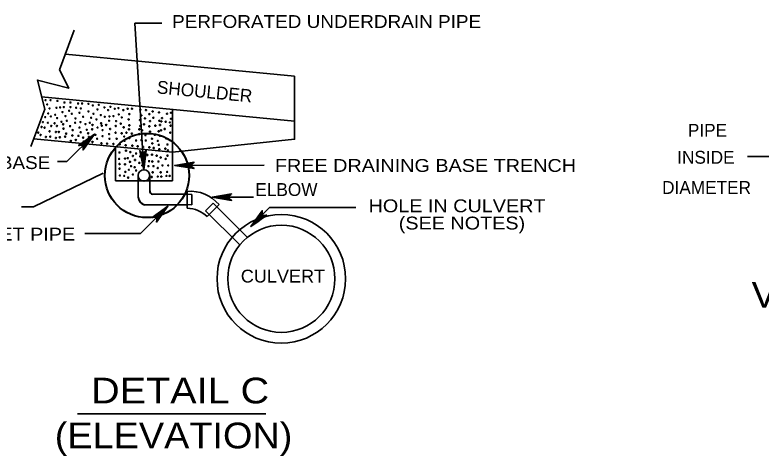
# Model space of a CAD drawing. Extents: x -48732 to -48696.6, y -117659.8 to -117637.8.
# Drawn here: x -48717.26 to -48710.3, y -117653.09 to -117648.97 of the extents above; entities that cross this region are included whole.
import ezdxf

# ---------------------------------------------------------------- set-up
doc = ezdxf.new("R2010")
doc.units = 0
doc.header["$LTSCALE"] = 0.048
doc.layers.add('1', color=7, linetype='Continuous', lineweight=25)
doc.layers.add('3', color=7, linetype='Continuous', lineweight=35)

msp = doc.modelspace()

# ---------------------------------------------------------------- linework, layer by layer
at = {"layer": '1', "lineweight": 40}
msp.add_circle((-48716.02774, -117650.47144), 0.39328, dxfattribs=at)
for centre, radius, end in [((-48716.03983, -117650.67442), 0.07, 262.57442), ((-48715.97183, -117650.61475), 0.03, 262.57441)]:
    msp.add_arc(centre, radius, 180, end, dxfattribs=at)
at = {"layer": '3'}
for p, q in [((-48716.05583, -117650.41717), (-48716.14042, -117649.0505)), ((-48716.14042, -117649.0505), (-48715.89042, -117649.0505)), ((-48716.70642, -117649.1155), (-48716.84342, -117649.4845)), ((-48716.78942, -117649.3385), (-48714.65075, -117649.5445)), ((-48717.01042, -117649.7365), (-48714.65075, -117649.96417)), ((-48716.98042, -117649.8515), (-48717.11042, -117650.1995)), ((-48716.77433, -117650.34067), (-48716.51842, -117650.08475)), ((-48716.32042, -117650.20225), (-48716.32042, -117650.5225)), ((-48715.78942, -117650.2535), (-48715.78942, -117650.5225)), ((-48710.10058, -117650.29358), (-48710.42558, -117650.29358)), ((-48716.86242, -117650.34067), (-48716.77433, -117650.34067)), ((-48715.76825, -117650.37733), (-48715.62425, -117650.37733)), ((-48715.73125, -117650.37733), (-48714.93433, -117650.374)), ((-48717.088, -117650.7625), (-48716.43608, -117650.44833)), ((-48716.32042, -117650.5225), (-48715.78942, -117650.5225)), ((-48716.10983, -117650.47117), (-48716.10983, -117650.67442)), ((-48716.00183, -117650.47117), (-48716.00183, -117650.61475)), ((-48715.97575, -117650.6445), (-48715.65158, -117650.6445)), ((-48715.65142, -117650.61958), (-48715.65242, -117650.77558)), ((-48715.65158, -117650.6445), (-48715.60942, -117650.64858)), ((-48715.60942, -117650.64858), (-48715.61042, -117650.74658)), ((-48716.04892, -117650.74383), (-48715.65158, -117650.74383)), ((-48715.65217, -117650.7425), (-48715.61042, -117650.74658)), ((-48715.41042, -117650.73058), (-48715.48042, -117650.80058)), ((-48715.35542, -117650.74358), (-48715.46642, -117650.85458)), ((-48715.09342, -117651.04658), (-48715.41042, -117650.73058)), ((-48717.19942, -117650.7625), (-48717.088, -117650.7625)), ((-48716.08808, -117651.01383), (-48715.83217, -117650.75792)), ((-48715.16342, -117651.11658), (-48715.48042, -117650.80058)), ((-48715.05842, -117650.94858), (-48714.88342, -117650.77158)), ((-48714.88342, -117650.77158), (-48714.07942, -117650.77158)), ((-48716.60667, -117651.01383), (-48716.08808, -117651.01383)), ((-48716.67542, -117652.69492), (-48714.92042, -117652.69492))]:
    msp.add_line(p, q, dxfattribs=at)
for points in [[(-48716.84342, -117649.4845), (-48716.75742, -117649.6575), (-48717.05042, -117649.5815), (-48716.98042, -117649.8515)], [(-48715.78942, -117650.2535), (-48714.65075, -117650.13283), (-48714.65075, -117649.5445)], [(-48717.08442, -117650.1285), (-48715.78942, -117650.2535), (-48715.78942, -117649.8545)], [(-48716.62442, -117650.23275), (-48716.51842, -117650.08475), (-48716.66642, -117650.19075), (-48716.66142, -117650.19075), (-48716.53142, -117650.09775), (-48716.62442, -117650.22775), (-48716.62342, -117650.22175), (-48716.54442, -117650.11075), (-48716.65542, -117650.18975), (-48716.64942, -117650.18875), (-48716.55742, -117650.12375), (-48716.62242, -117650.21575), (-48716.62242, -117650.20975), (-48716.57042, -117650.13675), (-48716.64342, -117650.18875), (-48716.63742, -117650.18775), (-48716.58242, -117650.14875), (-48716.62142, -117650.20375), (-48716.62142, -117650.19775), (-48716.59542, -117650.16175), (-48716.63142, -117650.18775), (-48716.62542, -117650.18675), (-48716.60842, -117650.17475), (-48716.62042, -117650.19175), (-48716.62442, -117650.23275), (-48716.62042, -117650.18675), (-48716.66642, -117650.19075)], [(-48716.09517, -117650.239), (-48716.05583, -117650.41717), (-48716.03525, -117650.23592), (-48716.03892, -117650.24117), (-48716.05667, -117650.39925), (-48716.091, -117650.24283), (-48716.08667, -117650.24767), (-48716.05767, -117650.38025), (-48716.04283, -117650.24533), (-48716.04558, -117650.25042), (-48716.05867, -117650.36225), (-48716.08342, -117650.25242), (-48716.07933, -117650.25617), (-48716.05967, -117650.34433), (-48716.04933, -117650.25467), (-48716.05308, -117650.25992), (-48716.06058, -117650.32633), (-48716.075, -117650.261), (-48716.07083, -117650.26475), (-48716.06158, -117650.30733), (-48716.05683, -117650.26408), (-48716.06058, -117650.26925), (-48716.0625, -117650.28942), (-48716.06658, -117650.26958), (-48716.09517, -117650.239), (-48716.06333, -117650.27342), (-48716.03525, -117650.23592)], [(-48715.58825, -117650.34733), (-48715.76825, -117650.37733), (-48715.58825, -117650.40733), (-48715.59325, -117650.40333), (-48715.75025, -117650.37733), (-48715.59225, -117650.35133), (-48715.59725, -117650.35533), (-48715.73125, -117650.37733), (-48715.59725, -117650.39933), (-48715.60225, -117650.39633), (-48715.71325, -117650.37733), (-48715.60225, -117650.35833), (-48715.60625, -117650.36233), (-48715.69525, -117650.37733), (-48715.60625, -117650.39233), (-48715.61125, -117650.38833), (-48715.67725, -117650.37733), (-48715.61125, -117650.36633), (-48715.61525, -117650.37033), (-48715.65825, -117650.37733), (-48715.61525, -117650.38433), (-48715.62025, -117650.38033), (-48715.64025, -117650.37733), (-48715.62025, -117650.37433), (-48715.58825, -117650.34733), (-48715.62425, -117650.37733), (-48715.58825, -117650.40733)], [(-48715.23842, -117650.64358), (-48715.41842, -117650.67358), (-48715.23842, -117650.70358), (-48715.24342, -117650.69958), (-48715.40042, -117650.67358), (-48715.24242, -117650.64758), (-48715.24742, -117650.65158), (-48715.38142, -117650.67358), (-48715.24742, -117650.69558), (-48715.25242, -117650.69258), (-48715.36342, -117650.67358), (-48715.25242, -117650.65458), (-48715.25642, -117650.65858), (-48715.34542, -117650.67358), (-48715.25642, -117650.68858), (-48715.26142, -117650.68458), (-48715.32742, -117650.67358), (-48715.26142, -117650.66258), (-48715.26542, -117650.66658), (-48715.30842, -117650.67358), (-48715.26542, -117650.68058), (-48715.27042, -117650.67658), (-48715.29042, -117650.67358), (-48715.27042, -117650.67058), (-48715.23842, -117650.64358), (-48715.27442, -117650.67358), (-48715.23842, -117650.70358)], [(-48715.41842, -117650.67358), (-48715.27442, -117650.67358), (-48715.03342, -117650.67258)], [(-48715.93817, -117650.90592), (-48715.83217, -117650.75792), (-48715.98017, -117650.86392), (-48715.97517, -117650.86392), (-48715.84517, -117650.77092), (-48715.93817, -117650.90092), (-48715.93717, -117650.89492), (-48715.85817, -117650.78392), (-48715.96917, -117650.86292), (-48715.96317, -117650.86192), (-48715.87117, -117650.79692), (-48715.93617, -117650.88892), (-48715.93617, -117650.88292), (-48715.88417, -117650.80992), (-48715.95717, -117650.86192), (-48715.95117, -117650.86092), (-48715.89617, -117650.82192), (-48715.93517, -117650.87692), (-48715.93517, -117650.87092), (-48715.90917, -117650.83492), (-48715.94517, -117650.86092), (-48715.93917, -117650.85992), (-48715.92217, -117650.84792), (-48715.93417, -117650.86492), (-48715.93817, -117650.90592), (-48715.93417, -117650.85992), (-48715.98017, -117650.86392)], [(-48714.95242, -117650.80058), (-48715.05842, -117650.94858), (-48714.91042, -117650.84258), (-48714.91542, -117650.84258), (-48715.04542, -117650.93558), (-48714.95242, -117650.80558), (-48714.95342, -117650.81158), (-48715.03242, -117650.92258), (-48714.92142, -117650.84358), (-48714.92742, -117650.84458), (-48715.01942, -117650.90958), (-48714.95442, -117650.81758), (-48714.95442, -117650.82358), (-48715.00642, -117650.89658), (-48714.93342, -117650.84458), (-48714.93942, -117650.84558), (-48714.99442, -117650.88458), (-48714.95542, -117650.82958), (-48714.95542, -117650.83558), (-48714.98142, -117650.87158), (-48714.94542, -117650.84558), (-48714.95142, -117650.84658), (-48714.96842, -117650.85858), (-48714.95642, -117650.84158), (-48714.95242, -117650.80058), (-48714.95642, -117650.84658), (-48714.91042, -117650.84258)]]:
    msp.add_lwpolyline(points, dxfattribs=at)
msp.add_lwpolyline([(-48714.98142, -117650.89358), (-48715.05842, -117650.94858), (-48715.00442, -117650.87158)], close=True, dxfattribs=at)
for centre, radius in [((-48716.97383, -117649.76792), 0.00515), ((-48716.92733, -117649.76792), 0.00515), ((-48716.86217, -117649.77417), 0.00515), ((-48716.95833, -117649.80825), 0.00515), ((-48716.93658, -117649.8455), 0.00515), ((-48716.8715, -117649.83933), 0.00515), ((-48716.83733, -117649.83625), 0.00515), ((-48716.80325, -117649.83308), 0.00515), ((-48716.797, -117649.78967), 0.00515), ((-48716.74117, -117649.78967), 0.00515), ((-48716.74117, -117649.83308), 0.00515), ((-48716.68842, -117649.83933), 0.00515), ((-48716.66983, -117649.799), 0.00515), ((-48716.645, -117649.8455), 0.00515), ((-48716.63258, -117649.799), 0.00515), ((-48716.57367, -117649.80208), 0.00515), ((-48716.53333, -117649.81758), 0.00515), ((-48716.4775, -117649.81142), 0.00515), ((-48716.42475, -117649.83625), 0.00515), ((-48716.36892, -117649.83), 0.00515), ((-48716.29442, -117649.84242), 0.00515), ((-48716.949, -117649.89208), 0.00515), ((-48716.88383, -117649.9045), 0.00515), ((-48716.81558, -117649.87967), 0.00515), ((-48716.75358, -117649.86725), 0.00515), ((-48716.72875, -117649.89517), 0.00515), ((-48716.65742, -117649.88583), 0.00515), ((-48716.57367, -117649.87342), 0.00515), ((-48716.52708, -117649.89517), 0.00515), ((-48716.48992, -117649.85483), 0.00515), ((-48716.45883, -117649.90758), 0.00515), ((-48716.39058, -117649.861), 0.00515), ((-48716.32858, -117649.84867), 0.00515), ((-48716.29133, -117649.90142), 0.00515), ((-48716.24792, -117649.861), 0.00515), ((-48716.20758, -117649.84867), 0.00515), ((-48716.19208, -117649.89825), 0.00515), ((-48716.16725, -117649.84867), 0.00515), ((-48716.08967, -117649.85792), 0.00515), ((-48716.08042, -117649.91067), 0.00515), ((-48716.03692, -117649.861), 0.00515), ((-48716.00592, -117649.89825), 0.00515), ((-48715.97492, -117649.87342), 0.00515), ((-48715.916, -117649.88275), 0.00515), ((-48715.8415, -117649.89517), 0.00515), ((-48715.80425, -117649.88583), 0.00515), ((-48716.99867, -117649.97275), 0.00515), ((-48716.97692, -117649.92625), 0.00515), ((-48716.95208, -117649.979), 0.00515), ((-48716.92417, -117649.92), 0.00515), ((-48716.89008, -117649.98517), 0.00515), ((-48716.86525, -117649.9355), 0.00515), ((-48716.82492, -117649.96967), 0.00515), ((-48716.78767, -117649.91692), 0.00515), ((-48716.77533, -117649.96033), 0.00515), ((-48716.69775, -117649.979), 0.00515), ((-48716.69467, -117649.93867), 0.00515), ((-48716.64808, -117649.97275), 0.00515), ((-48716.62325, -117649.92308), 0.00515), ((-48716.56125, -117649.979), 0.00515), ((-48716.54883, -117649.93242), 0.00515), ((-48716.49917, -117649.94792), 0.00515), ((-48716.45575, -117649.98517), 0.00515), ((-48716.42167, -117649.92308), 0.00515), ((-48716.38133, -117649.96033), 0.00515), ((-48716.37817, -117649.92), 0.00515), ((-48716.341, -117649.91692), 0.00515), ((-48716.31617, -117649.9635), 0.00515), ((-48716.26342, -117649.92933), 0.00515), ((-48716.19825, -117649.94792), 0.00515), ((-48716.09283, -117649.95417), 0.00515), ((-48716.04625, -117649.93867), 0.00515), ((-48715.99975, -117649.9635), 0.00515), ((-48715.96875, -117649.93242), 0.00515), ((-48715.91283, -117649.96033), 0.00515), ((-48715.89425, -117649.96658), 0.00515), ((-48715.88808, -117649.9355), 0.00515), ((-48715.85392, -117649.96967), 0.00515), ((-48715.81358, -117649.97592), 0.00515), ((-48715.80425, -117649.94175), 0.00515), ((-48717.01108, -117650.01933), 0.00515), ((-48716.98317, -117650.0255), 0.00515), ((-48716.92108, -117650.01), 0.00515), ((-48716.86833, -117650.01), 0.00515), ((-48716.80942, -117649.9945), 0.00515), ((-48716.80633, -117650.03483), 0.00515), ((-48716.74446, -117650.01069), 0.00515), ((-48716.72096, -117650.04778), 0.00515), ((-48716.65704, -117650.02419), 0.00515), ((-48716.60158, -117649.99142), 0.00515), ((-48716.58979, -117650.04436), 0.00515), ((-48716.53929, -117650.04103), 0.00515), ((-48716.53642, -117650.00067), 0.00515), ((-48716.48888, -117650.02419), 0.00515), ((-48716.44958, -117650.00692), 0.00515), ((-48716.44179, -117650.04778), 0.00515), ((-48716.40813, -117650.00061), 0.00515), ((-48716.372, -117650.03792), 0.00515), ((-48716.31925, -117650.01), 0.00515), ((-48716.27275, -117649.98825), 0.00515), ((-48716.24483, -117650.02242), 0.00515), ((-48716.19517, -117650.04108), 0.00515), ((-48716.19208, -117650.00383), 0.00515), ((-48716.099, -117650.04108), 0.00515), ((-48716.08967, -117650.01), 0.00515), ((-48716.07417, -117650.05033), 0.00515), ((-48716.05558, -117649.9945), 0.00515), ((-48716.00592, -117650.01308), 0.00515), ((-48715.95008, -117650.00692), 0.00515), ((-48715.90667, -117650.00067), 0.00515), ((-48715.89733, -117650.05033), 0.00515), ((-48715.86325, -117650.03792), 0.00515), ((-48715.80742, -117650.00692), 0.00515), ((-48717.04208, -117650.07208), 0.00515), ((-48717.02033, -117650.09383), 0.00515), ((-48716.97075, -117650.11242), 0.00515), ((-48716.93658, -117650.05967), 0.00515), ((-48716.93042, -117650.10933), 0.00515), ((-48716.87767, -117650.06592), 0.00515), ((-48716.87767, -117650.12175), 0.00515), ((-48716.84975, -117650.06592), 0.00515), ((-48716.84042, -117650.11558), 0.00515), ((-48716.79083, -117650.10933), 0.00515), ((-48716.7815, -117650.08142), 0.00515), ((-48716.72429, -117650.09828), 0.00515), ((-48716.66713, -117650.10161), 0.00515), ((-48716.64696, -117650.06794), 0.00515), ((-48716.62338, -117650.11844), 0.00515), ((-48716.57629, -117650.07803), 0.00515), ((-48716.56954, -117650.11169), 0.00515), ((-48716.50904, -117650.09153), 0.00515), ((-48716.44179, -117650.10494), 0.00515), ((-48716.38121, -117650.08478), 0.00515), ((-48716.32063, -117650.07136), 0.00515), ((-48716.26346, -117650.07803), 0.00515), ((-48716.23996, -117650.10836), 0.00515), ((-48716.21971, -117650.07136), 0.00515), ((-48716.19279, -117650.12178), 0.00515), ((-48716.16929, -117650.08144), 0.00515), ((-48716.09863, -117650.08478), 0.00515), ((-48716.04146, -117650.09486), 0.00515), ((-48715.99975, -117650.06275), 0.00515), ((-48715.95404, -117650.09153), 0.00515), ((-48715.91908, -117650.05967), 0.00515), ((-48715.90688, -117650.10161), 0.00515), ((-48715.8105, -117650.07208), 0.00515), ((-48716.73808, -117650.14967), 0.00515), ((-48716.6915, -117650.14033), 0.00515), ((-48716.61708, -117650.15592), 0.00515), ((-48716.53642, -117650.159), 0.00515), ((-48716.49221, -117650.12853), 0.00515), ((-48716.45267, -117650.17142), 0.00515), ((-48716.39992, -117650.1745), 0.00515), ((-48716.37788, -117650.12853), 0.00515), ((-48716.341, -117650.17758), 0.00515), ((-48716.31054, -117650.12853), 0.00515), ((-48716.282, -117650.18075), 0.00515), ((-48716.23654, -117650.14878), 0.00515), ((-48716.22617, -117650.19), 0.00515), ((-48716.16417, -117650.19317), 0.00515), ((-48716.12896, -117650.14536), 0.00515), ((-48716.07846, -117650.14203), 0.00515), ((-48716.03813, -117650.14536), 0.00515), ((-48715.98088, -117650.12853), 0.00515), ((-48715.97754, -117650.17228), 0.00515), ((-48715.92713, -117650.14878), 0.00515), ((-48715.91704, -117650.18578), 0.00515), ((-48715.84971, -117650.12519), 0.00515), ((-48715.83629, -117650.18236), 0.00515), ((-48716.28367, -117650.25641), 0.00515), ((-48716.22317, -117650.23958), 0.00515), ((-48716.18275, -117650.25308), 0.00515), ((-48716.1145, -117650.19933), 0.00515), ((-48716.065, -117650.25983), 0.00515), ((-48716.06492, -117650.20558), 0.00515), ((-48716.00592, -117650.20867), 0.00515), ((-48715.96558, -117650.21483), 0.00515), ((-48715.91283, -117650.22725), 0.00515), ((-48715.857, -117650.22108), 0.00515), ((-48715.83225, -117650.23658), 0.00515), ((-48716.28708, -117650.317), 0.00515), ((-48716.23325, -117650.31366), 0.00515), ((-48716.20633, -117650.31025), 0.00515), ((-48716.15925, -117650.29008), 0.00515), ((-48716.13908, -117650.32708), 0.00515), ((-48716.12892, -117650.2665), 0.00515), ((-48716.09192, -117650.2935), 0.00515), ((-48716.02467, -117650.28), 0.00515), ((-48715.98092, -117650.27666), 0.00515), ((-48715.93725, -117650.28675), 0.00515), ((-48715.90025, -117650.30358), 0.00515), ((-48715.85308, -117650.317), 0.00515), ((-48715.83633, -117650.28675), 0.00515), ((-48716.28367, -117650.36416), 0.00515), ((-48716.23325, -117650.3675), 0.00515), ((-48716.18617, -117650.34391), 0.00515), ((-48716.17608, -117650.38433), 0.00515), ((-48716.14242, -117650.39441), 0.00515), ((-48716.09867, -117650.35408), 0.00515), ((-48716.07175, -117650.37758), 0.00515), ((-48716.05158, -117650.33383), 0.00515), ((-48716.01458, -117650.38433), 0.00515), ((-48716.00783, -117650.33725), 0.00515), ((-48715.97758, -117650.34058), 0.00515), ((-48715.9675, -117650.38433), 0.00515), ((-48715.92717, -117650.40116), 0.00515), ((-48715.92042, -117650.34058), 0.00515), ((-48715.88342, -117650.37758), 0.00515), ((-48715.82958, -117650.37758), 0.00515), ((-48716.28367, -117650.40791), 0.00515), ((-48716.28033, -117650.47183), 0.00515), ((-48716.22983, -117650.43816), 0.00515), ((-48716.19625, -117650.418), 0.00515), ((-48716.15925, -117650.46175), 0.00515), ((-48716.12892, -117650.42475), 0.00515), ((-48716.05582, -117650.4712), 0.054), ((-48715.97425, -117650.44158), 0.00515), ((-48715.90025, -117650.44158), 0.00515), ((-48715.83967, -117650.43816), 0.00515), ((-48716.24, -117650.47525), 0.00515), ((-48716.20292, -117650.49208), 0.00515), ((-48715.98433, -117650.48533), 0.00515), ((-48715.92717, -117650.48191), 0.00515), ((-48715.8935, -117650.48191), 0.00515), ((-48715.84642, -117650.47525), 0.00515), ((-48715.81608, -117650.47525), 0.00515), ((-48714.77442, -117651.43558), 0.6), ((-48714.77442, -117651.43558), 0.5)]:
    msp.add_circle(centre, radius, dxfattribs=at)
for centre, radius, start, end in [((-48715.62283, -117650.96663), 0.34823, 39.83169, 94.70885), ((-48715.66992, -117651.07528), 0.3002, 47.32058, 86.6572)]:
    msp.add_arc(centre, radius, start, end, dxfattribs=at)

# ---------------------------------------------------------------- texts
for s, height, width, p in [('PERFORATED UNDERDRAIN PIPE', 0.12, 1.1, (-48715.79342, -117649.0945)), ('FREE DRAINING BASE', 0.12, 1.1, (-48718.83258, -117650.41125)), ('FREE DRAINING BASE TRENCH', 0.12, 1.15, (-48714.83408, -117650.438)), ('HOLE IN CULVERT', 0.12, 1.15, (-48713.96042, -117650.81458)), ('(SEE NOTES)', 0.12, 1.15, (-48713.67842, -117650.97558)), ('OUTLET PIPE', 0.12, 1.15, (-48717.89742, -117651.079)), ('CULVERT', 0.12, 1.05, (-48715.15242, -117651.47058)), ('VARMINT SCREEN', 0.24, 1.1, (-48710.3865, -117651.70567)), ('DETAIL C', 0.24, 1.15, (-48716.54908, -117652.59867)), ('(ELEVATION)', 0.24, 1.1, (-48716.88825, -117653.01825))]:
    msp.add_text(s, height=height, dxfattribs=dict(at, width=width)).set_placement(p)
msp.add_text('SHOULDER', height=0.12, rotation=354.497, dxfattribs=at).set_placement((-48715.93942, -117649.7045))
for s, p in [('PIPE', (-48710.98158, -117650.10958)), ('INSIDE', (-48711.08058, -117650.36158)), ('DIAMETER', (-48711.22158, -117650.64358)), ('ELBOW', (-48715.01642, -117650.66258))]:
    msp.add_text(s, height=0.12, dxfattribs=at).set_placement(p)

doc.saveas('drawing.dxf')
